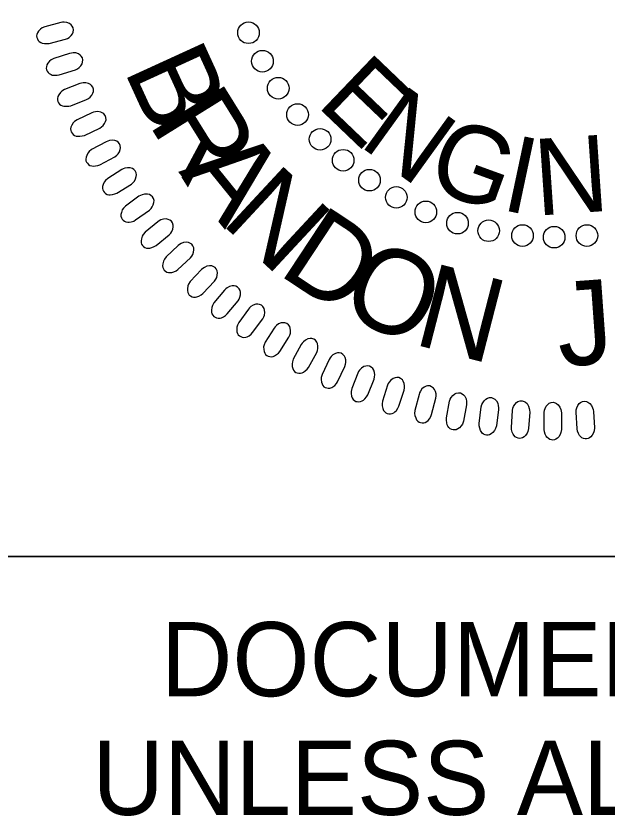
# Model space of a CAD drawing. Extents: x 505602 to 507705, y 483109 to 484209.
# Drawn here: x 507079.4 to 507123.2, y 484026.9 to 484086.2 of the extents above; entities that cross this region are included whole.
import ezdxf

# ---------------------------------------------------------------- set-up
doc = ezdxf.new("R2010")
doc.units = 0
for name, color, linetype in [('Sheet PE Seal Cell', 7, 'Continuous'), ('Sheet Profile CELL', 7, 'Continuous'), ('Sheet Sticker Exception Certification CELL', 7, 'Continuous')]:
    doc.layers.add(name, color=color, linetype=linetype)

msp = doc.modelspace()

# ---------------------------------------------------------------- linework, layer by layer
at = {"layer": 'Sheet PE Seal Cell'}
for points in [[(507082.689, 484085.753), (507081.501, 484085.449), (507081.298, 484085.358), (507081.175, 484085.273), (507081.039, 484085.122), (507080.957, 484085), (507080.907, 484084.872), (507080.895, 484084.761), (507080.903, 484084.647), (507080.95, 484084.544), (507081.009, 484084.435), (507081.093, 484084.349), (507081.216, 484084.272), (507081.308, 484084.234), (507081.469, 484084.206), (507081.658, 484084.193), (507081.818, 484084.21), (507083.037, 484084.515), (507083.196, 484084.579), (507083.32, 484084.657), (507083.452, 484084.784), (507083.56, 484084.927), (507083.613, 484085.04), (507083.632, 484085.208), (507083.614, 484085.358), (507083.538, 484085.492), (507083.464, 484085.582), (507083.336, 484085.68), (507083.142, 484085.753), (507082.951, 484085.775), (507082.818, 484085.771)], [(507083.343, 484083.469), (507082.176, 484083.09), (507081.979, 484082.987), (507081.862, 484082.895), (507081.735, 484082.735), (507081.661, 484082.609), (507081.62, 484082.478), (507081.615, 484082.366), (507081.63, 484082.253), (507081.684, 484082.153), (507081.749, 484082.049), (507081.838, 484081.967), (507081.966, 484081.899), (507082.059, 484081.866), (507082.223, 484081.849), (507082.412, 484081.847), (507082.571, 484081.875), (507083.768, 484082.256), (507083.922, 484082.33), (507084.042, 484082.415), (507084.165, 484082.55), (507084.263, 484082.699), (507084.31, 484082.817), (507084.318, 484082.984), (507084.291, 484083.133), (507084.207, 484083.263), (507084.127, 484083.347), (507083.993, 484083.437), (507083.795, 484083.498), (507083.603, 484083.507), (507083.471, 484083.495)], [(507084.102, 484081.232), (507082.961, 484080.781), (507082.77, 484080.665), (507082.659, 484080.566), (507082.543, 484080.399), (507082.477, 484080.268), (507082.444, 484080.134), (507082.446, 484080.023), (507082.468, 484079.911), (507082.528, 484079.815), (507082.6, 484079.714), (507082.693, 484079.639), (507082.825, 484079.578), (507082.921, 484079.552), (507083.086, 484079.544), (507083.274, 484079.555), (507083.431, 484079.592), (507084.602, 484080.047), (507084.752, 484080.131), (507084.865, 484080.224), (507084.98, 484080.366), (507085.069, 484080.522), (507085.108, 484080.641), (507085.105, 484080.81), (507085.069, 484080.956), (507084.977, 484081.08), (507084.892, 484081.159), (507084.753, 484081.241), (507084.551, 484081.289), (507084.359, 484081.286), (507084.228, 484081.266)], [(507085.001, 484079.073), (507083.891, 484078.551), (507083.709, 484078.423), (507083.604, 484078.317), (507083.499, 484078.143), (507083.441, 484078.008), (507083.416, 484077.873), (507083.425, 484077.761), (507083.454, 484077.651), (507083.52, 484077.559), (507083.598, 484077.463), (507083.697, 484077.394), (507083.832, 484077.342), (507083.929, 484077.321), (507084.093, 484077.324), (507084.281, 484077.347), (507084.435, 484077.394), (507085.576, 484077.922), (507085.719, 484078.015), (507085.827, 484078.114), (507085.932, 484078.263), (507086.012, 484078.424), (507086.043, 484078.546), (507086.03, 484078.714), (507085.984, 484078.858), (507085.884, 484078.976), (507085.794, 484079.049), (507085.651, 484079.122), (507085.446, 484079.157), (507085.255, 484079.143), (507085.125, 484079.114)], [(507086.049, 484076.924), (507084.973, 484076.333), (507084.799, 484076.195), (507084.702, 484076.082), (507084.607, 484075.902), (507084.558, 484075.764), (507084.542, 484075.628), (507084.557, 484075.516), (507084.594, 484075.408), (507084.666, 484075.32), (507084.75, 484075.23), (507084.852, 484075.167), (507084.99, 484075.123), (507085.089, 484075.109), (507085.252, 484075.122), (507085.438, 484075.156), (507085.589, 484075.213), (507086.694, 484075.811), (507086.832, 484075.913), (507086.932, 484076.02), (507087.029, 484076.175), (507087.097, 484076.34), (507087.121, 484076.464), (507087.097, 484076.63), (507087.043, 484076.771), (507086.936, 484076.883), (507086.842, 484076.951), (507086.693, 484077.014), (507086.487, 484077.037), (507086.297, 484077.01), (507086.169, 484076.973)], [(507087.205, 484074.85), (507086.169, 484074.192), (507086.003, 484074.043), (507085.914, 484073.925), (507085.83, 484073.739), (507085.79, 484073.598), (507085.783, 484073.46), (507085.805, 484073.351), (507085.848, 484073.245), (507085.926, 484073.162), (507086.015, 484073.077), (507086.121, 484073.02), (507086.261, 484072.985), (507086.36, 484072.978), (507086.523, 484073.001), (507086.707, 484073.047), (507086.853, 484073.113), (507087.919, 484073.779), (507088.05, 484073.889), (507088.144, 484074.003), (507088.23, 484074.163), (507088.288, 484074.333), (507088.304, 484074.458), (507088.27, 484074.622), (507088.207, 484074.759), (507088.093, 484074.864), (507087.995, 484074.925), (507087.842, 484074.98), (507087.635, 484074.99), (507087.447, 484074.95), (507087.322, 484074.906)], [(507088.482, 484072.875), (507087.488, 484072.153), (507087.333, 484071.994), (507087.25, 484071.87), (507087.179, 484071.68), (507087.148, 484071.537), (507087.149, 484071.399), (507087.178, 484071.291), (507087.228, 484071.188), (507087.31, 484071.11), (507087.405, 484071.03), (507087.515, 484070.98), (507087.657, 484070.955), (507087.756, 484070.953), (507087.917, 484070.987), (507088.097, 484071.043), (507088.24, 484071.119), (507089.261, 484071.851), (507089.385, 484071.969), (507089.471, 484072.088), (507089.548, 484072.254), (507089.595, 484072.426), (507089.603, 484072.552), (507089.559, 484072.714), (507089.487, 484072.847), (507089.367, 484072.944), (507089.265, 484073), (507089.11, 484073.045), (507088.903, 484073.041), (507088.717, 484072.99), (507088.595, 484072.939)], [(507089.885, 484070.993), (507088.939, 484070.211), (507088.794, 484070.043), (507088.72, 484069.914), (507088.661, 484069.719), (507088.638, 484069.574), (507088.648, 484069.437), (507088.684, 484069.331), (507088.74, 484069.232), (507088.827, 484069.159), (507088.926, 484069.085), (507089.039, 484069.042), (507089.182, 484069.026), (507089.282, 484069.03), (507089.44, 484069.074), (507089.616, 484069.142), (507089.754, 484069.226), (507090.727, 484070.021), (507090.844, 484070.146), (507090.922, 484070.27), (507090.988, 484070.441), (507091.025, 484070.616), (507091.024, 484070.742), (507090.97, 484070.901), (507090.89, 484071.029), (507090.764, 484071.118), (507090.659, 484071.167), (507090.501, 484071.202), (507090.295, 484071.187), (507090.113, 484071.124), (507089.994, 484071.064)], [(507091.395, 484069.222), (507090.5, 484068.383), (507090.366, 484068.206), (507090.3, 484068.072), (507090.253, 484067.874), (507090.24, 484067.728), (507090.258, 484067.592), (507090.301, 484067.488), (507090.363, 484067.393), (507090.454, 484067.325), (507090.558, 484067.258), (507090.673, 484067.223), (507090.818, 484067.215), (507090.916, 484067.226), (507091.072, 484067.279), (507091.244, 484067.358), (507091.375, 484067.451), (507092.296, 484068.305), (507092.405, 484068.438), (507092.476, 484068.566), (507092.531, 484068.74), (507092.556, 484068.918), (507092.548, 484069.043), (507092.484, 484069.199), (507092.396, 484069.321), (507092.265, 484069.403), (507092.157, 484069.445), (507091.997, 484069.47), (507091.792, 484069.441), (507091.614, 484069.367), (507091.5, 484069.3)], [(507093.131, 484067.444), (507092.29, 484066.55), (507092.167, 484066.365), (507092.11, 484066.227), (507092.075, 484066.027), (507092.071, 484065.88), (507092.098, 484065.745), (507092.147, 484065.645), (507092.215, 484065.553), (507092.31, 484065.491), (507092.419, 484065.431), (507092.535, 484065.403), (507092.68, 484065.404), (507092.778, 484065.421), (507092.93, 484065.484), (507093.096, 484065.574), (507093.222, 484065.675), (507094.088, 484066.586), (507094.187, 484066.724), (507094.25, 484066.857), (507094.294, 484067.035), (507094.308, 484067.213), (507094.292, 484067.338), (507094.219, 484067.489), (507094.123, 484067.606), (507093.987, 484067.679), (507093.876, 484067.714), (507093.716, 484067.729), (507093.513, 484067.687), (507093.34, 484067.602), (507093.23, 484067.528)], [(507094.821, 484065.914), (507094.038, 484064.969), (507093.927, 484064.776), (507093.878, 484064.635), (507093.856, 484064.433), (507093.862, 484064.286), (507093.897, 484064.154), (507093.952, 484064.056), (507094.026, 484063.969), (507094.124, 484063.914), (507094.236, 484063.86), (507094.354, 484063.839), (507094.499, 484063.85), (507094.596, 484063.872), (507094.743, 484063.945), (507094.903, 484064.045), (507095.023, 484064.154), (507095.83, 484065.117), (507095.921, 484065.262), (507095.974, 484065.399), (507096.008, 484065.578), (507096.011, 484065.757), (507095.986, 484065.881), (507095.903, 484066.027), (507095.801, 484066.138), (507095.661, 484066.202), (507095.547, 484066.23), (507095.386, 484066.235), (507095.187, 484066.18), (507095.019, 484066.085), (507094.914, 484066.004)], [(507096.601, 484064.514), (507095.88, 484063.521), (507095.781, 484063.322), (507095.741, 484063.178), (507095.732, 484062.975), (507095.747, 484062.828), (507095.79, 484062.698), (507095.851, 484062.605), (507095.93, 484062.522), (507096.033, 484062.473), (507096.148, 484062.427), (507096.267, 484062.413), (507096.41, 484062.433), (507096.506, 484062.462), (507096.648, 484062.544), (507096.802, 484062.654), (507096.914, 484062.769), (507097.659, 484063.781), (507097.74, 484063.931), (507097.786, 484064.071), (507097.808, 484064.252), (507097.8, 484064.432), (507097.767, 484064.553), (507097.676, 484064.694), (507097.566, 484064.798), (507097.422, 484064.854), (507097.308, 484064.875), (507097.147, 484064.869), (507096.95, 484064.802), (507096.79, 484064.696), (507096.69, 484064.609)], [(507098.503, 484063.1), (507097.846, 484062.064), (507097.759, 484061.859), (507097.728, 484061.714), (507097.732, 484061.51), (507097.756, 484061.366), (507097.808, 484061.238), (507097.874, 484061.148), (507097.959, 484061.072), (507098.063, 484061.028), (507098.181, 484060.989), (507098.301, 484060.984), (507098.443, 484061.012), (507098.536, 484061.047), (507098.673, 484061.137), (507098.82, 484061.256), (507098.924, 484061.379), (507099.604, 484062.436), (507099.676, 484062.591), (507099.713, 484062.733), (507099.723, 484062.916), (507099.703, 484063.094), (507099.663, 484063.213), (507099.564, 484063.349), (507099.448, 484063.445), (507099.3, 484063.491), (507099.185, 484063.505), (507099.025, 484063.49), (507098.833, 484063.411), (507098.679, 484063.295), (507098.585, 484063.202)], [(507100.521, 484061.885), (507099.93, 484060.81), (507099.857, 484060.6), (507099.835, 484060.452), (507099.852, 484060.25), (507099.884, 484060.106), (507099.944, 484059.982), (507100.016, 484059.897), (507100.105, 484059.826), (507100.212, 484059.789), (507100.332, 484059.758), (507100.452, 484059.759), (507100.592, 484059.797), (507100.683, 484059.837), (507100.814, 484059.936), (507100.953, 484060.065), (507101.05, 484060.194), (507101.662, 484061.291), (507101.723, 484061.45), (507101.751, 484061.595), (507101.75, 484061.777), (507101.72, 484061.954), (507101.673, 484062.071), (507101.564, 484062.199), (507101.442, 484062.288), (507101.292, 484062.325), (507101.176, 484062.332), (507101.017, 484062.306), (507100.831, 484062.215), (507100.685, 484062.09), (507100.596, 484061.991)], [(507102.58, 484060.778), (507102.058, 484059.669), (507101.998, 484059.454), (507101.986, 484059.306), (507102.015, 484059.104), (507102.056, 484058.963), (507102.124, 484058.844), (507102.201, 484058.763), (507102.295, 484058.697), (507102.404, 484058.668), (507102.525, 484058.644), (507102.645, 484058.653), (507102.783, 484058.699), (507102.871, 484058.745), (507102.995, 484058.852), (507103.126, 484058.989), (507103.215, 484059.124), (507103.757, 484060.257), (507103.808, 484060.421), (507103.827, 484060.566), (507103.814, 484060.749), (507103.773, 484060.923), (507103.718, 484061.036), (507103.602, 484061.157), (507103.474, 484061.239), (507103.323, 484061.267), (507103.206, 484061.266), (507103.049, 484061.23), (507102.869, 484061.128), (507102.732, 484060.993), (507102.65, 484060.889)], [(507104.708, 484059.77), (507104.256, 484058.63), (507104.21, 484058.412), (507104.207, 484058.263), (507104.249, 484058.064), (507104.298, 484057.926), (507104.374, 484057.811), (507104.456, 484057.735), (507104.553, 484057.675), (507104.664, 484057.652), (507104.787, 484057.636), (507104.906, 484057.652), (507105.04, 484057.708), (507105.125, 484057.759), (507105.243, 484057.874), (507105.364, 484058.018), (507105.444, 484058.158), (507105.914, 484059.324), (507105.956, 484059.49), (507105.965, 484059.636), (507105.941, 484059.817), (507105.888, 484059.988), (507105.827, 484060.099), (507105.703, 484060.212), (507105.571, 484060.286), (507105.418, 484060.303), (507105.302, 484060.295), (507105.147, 484060.25), (507104.974, 484060.136), (507104.845, 484059.994), (507104.77, 484059.885)], [(507106.917, 484058.868), (507106.537, 484057.701), (507106.505, 484057.481), (507106.511, 484057.332), (507106.565, 484057.136), (507106.624, 484057.002), (507106.706, 484056.891), (507106.793, 484056.821), (507106.894, 484056.767), (507107.006, 484056.752), (507107.13, 484056.743), (507107.247, 484056.767), (507107.378, 484056.831), (507107.459, 484056.888), (507107.57, 484057.009), (507107.682, 484057.161), (507107.753, 484057.306), (507108.149, 484058.498), (507108.18, 484058.667), (507108.18, 484058.814), (507108.144, 484058.993), (507108.081, 484059.16), (507108.013, 484059.266), (507107.882, 484059.372), (507107.746, 484059.437), (507107.592, 484059.445), (507107.477, 484059.43), (507107.325, 484059.375), (507107.159, 484059.251), (507107.039, 484059.1), (507106.971, 484058.986)], [(507109.25, 484058.195), (507108.944, 484057.007), (507108.926, 484056.786), (507108.941, 484056.637), (507109.008, 484056.444), (507109.074, 484056.314), (507109.164, 484056.209), (507109.255, 484056.144), (507109.358, 484056.097), (507109.472, 484056.089), (507109.595, 484056.088), (507109.711, 484056.119), (507109.837, 484056.19), (507109.915, 484056.252), (507110.018, 484056.381), (507110.12, 484056.54), (507110.182, 484056.689), (507110.502, 484057.904), (507110.522, 484058.073), (507110.513, 484058.22), (507110.466, 484058.397), (507110.393, 484058.56), (507110.318, 484058.661), (507110.181, 484058.759), (507110.042, 484058.815), (507109.886, 484058.814), (507109.773, 484058.791), (507109.625, 484058.727), (507109.467, 484058.592), (507109.357, 484058.435), (507109.296, 484058.317)], [(507112.772, 484057.407), (507112.541, 484056.202), (507112.463, 484055.994), (507112.386, 484055.866), (507112.244, 484055.721), (507112.128, 484055.632), (507112.003, 484055.574), (507111.892, 484055.554), (507111.778, 484055.557), (507111.673, 484055.597), (507111.56, 484055.649), (507111.469, 484055.727), (507111.385, 484055.845), (507111.341, 484055.934), (507111.303, 484056.094), (507111.278, 484056.282), (507111.286, 484056.442), (507111.514, 484057.678), (507111.568, 484057.841), (507111.639, 484057.969), (507111.757, 484058.109), (507111.893, 484058.225), (507112.003, 484058.285), (507112.168, 484058.314), (507112.32, 484058.306), (507112.458, 484058.238), (507112.552, 484058.17), (507112.658, 484058.049), (507112.743, 484057.859), (507112.776, 484057.67), (507112.781, 484057.538)], [(507115.138, 484057.081), (507114.983, 484055.864), (507114.919, 484055.652), (507114.849, 484055.519), (507114.717, 484055.365), (507114.607, 484055.268), (507114.485, 484055.203), (507114.377, 484055.177), (507114.263, 484055.172), (507114.155, 484055.205), (507114.039, 484055.25), (507113.943, 484055.322), (507113.852, 484055.435), (507113.802, 484055.521), (507113.754, 484055.678), (507113.718, 484055.864), (507113.715, 484056.025), (507113.866, 484057.272), (507113.909, 484057.437), (507113.972, 484057.571), (507114.08, 484057.717), (507114.209, 484057.842), (507114.316, 484057.909), (507114.479, 484057.949), (507114.63, 484057.949), (507114.773, 484057.891), (507114.871, 484057.828), (507114.985, 484057.714), (507115.081, 484057.531), (507115.126, 484057.344), (507115.139, 484057.211)], [(507117.455, 484056.884), (507117.377, 484055.659), (507117.326, 484055.443), (507117.265, 484055.307), (507117.143, 484055.144), (507117.039, 484055.041), (507116.922, 484054.969), (507116.815, 484054.935), (507116.701, 484054.923), (507116.591, 484054.95), (507116.474, 484054.987), (507116.373, 484055.053), (507116.275, 484055.16), (507116.22, 484055.243), (507116.162, 484055.397), (507116.114, 484055.579), (507116.102, 484055.74), (507116.173, 484056.995), (507116.207, 484057.162), (507116.261, 484057.299), (507116.36, 484057.452), (507116.48, 484057.585), (507116.583, 484057.658), (507116.743, 484057.708), (507116.894, 484057.718), (507117.041, 484057.669), (507117.141, 484057.613), (507117.262, 484057.505), (507117.37, 484057.328), (507117.427, 484057.144), (507117.448, 484057.014)], [(507122.175, 484056.934), (507122.251, 484055.71), (507122.228, 484055.489), (507122.185, 484055.346), (507122.083, 484055.169), (507121.994, 484055.054), (507121.886, 484054.968), (507121.785, 484054.921), (507121.674, 484054.894), (507121.561, 484054.908), (507121.44, 484054.93), (507121.331, 484054.983), (507121.22, 484055.076), (507121.156, 484055.152), (507121.08, 484055.297), (507121.009, 484055.472), (507120.976, 484055.63), (507120.89, 484056.884), (507120.902, 484057.055), (507120.938, 484057.197), (507121.018, 484057.361), (507121.121, 484057.508), (507121.213, 484057.593), (507121.366, 484057.663), (507121.514, 484057.692), (507121.665, 484057.662), (507121.773, 484057.619), (507121.906, 484057.527), (507122.036, 484057.365), (507122.115, 484057.19), (507122.153, 484057.063)], [(507119.808, 484056.812), (507119.808, 484055.585), (507119.77, 484055.366), (507119.718, 484055.226), (507119.606, 484055.056), (507119.508, 484054.947), (507119.396, 484054.867), (507119.292, 484054.827), (507119.18, 484054.808), (507119.068, 484054.828), (507118.948, 484054.857), (507118.843, 484054.917), (507118.738, 484055.017), (507118.679, 484055.097), (507118.611, 484055.247), (507118.552, 484055.426), (507118.529, 484055.586), (507118.522, 484056.842), (507118.545, 484057.011), (507118.59, 484057.151), (507118.679, 484057.311), (507118.791, 484057.45), (507118.889, 484057.53), (507119.046, 484057.59), (507119.196, 484057.61), (507119.345, 484057.57), (507119.45, 484057.52), (507119.577, 484057.421), (507119.696, 484057.251), (507119.764, 484057.071), (507119.793, 484056.941)]]:
    msp.add_lwpolyline(points, close=True, dxfattribs=at)
for centre in [(507096.606, 484085.001), (507097.641, 484082.889), (507098.81, 484080.886), (507100.242, 484078.933), (507101.914, 484077.1), (507103.625, 484075.546), (507105.576, 484074.071), (507107.566, 484072.796), (507109.755, 484071.719), (507112.104, 484070.882), (507114.413, 484070.324), (507116.921, 484069.964), (507121.699, 484069.963), (507119.27, 484069.844)]:
    msp.add_circle(centre, 0.801, dxfattribs=at)
at = {"layer": 'Sheet Profile CELL'}
msp.add_lwpolyline([(507069.03, 484158.662), (507169.08, 484158.662), (507169.08, 484046.162), (507069.03, 484046.162)], close=True, dxfattribs=at)
at = {"layer": 'Sheet Sticker Exception Certification CELL'}
msp.add_line((507069.03, 484046.162), (507269.067, 484046.162), dxfattribs=at)
msp.add_line((507069.03, 484046.162), (507269.067, 484046.162), dxfattribs=at)

# ---------------------------------------------------------------- texts
at = {"layer": 'Sheet PE Seal Cell'}
for s, height, rotation, p in [('B', 6.236, 294.5897, (507087.323, 484082.272)), ('E', 5.669, 316.26559, (507101.563, 484079.651)), ('R', 6.236, 301.86473, (507089.134, 484078.316)), ('N', 5.669, 324.20538, (507104.698, 484076.696)), ('G', 5.669, 340.08498, (507109.592, 484073.597)), ('I', 5.669, 348.02477, (507115.221, 484071.908)), ('N', 5.669, 3.90437, (507117.974, 484071.435)), ('A', 6.236, 308.98157, (507091.377, 484074.698)), ('N', 6.236, 317.09274, (507094.456, 484070.95)), ('D', 6.236, 326.58243, (507098.686, 484067.169)), ('O', 6.236, 335.45066, (507103.152, 484064.311)), ('N', 6.236, 345.5505, (507108.704, 484061.939)), ('J', 6.236, 4.1457, (507119.655, 484060.247))]:
    msp.add_text(s, height=height, rotation=rotation, dxfattribs=at).set_placement(p)
at = {"layer": 'Sheet Sticker Exception Certification CELL'}
for s, p in [('DOCUMENT NOT CONSIDERED FINAL', (507090.101, 484035.816)), ('DOCUMENT NOT CONSIDERED FINAL', (507090.101, 484035.816)), ('UNLESS ALL SIGNATURES COMPLETED', (507085.03, 484027.016)), ('UNLESS ALL SIGNATURES COMPLETED', (507085.03, 484027.016))]:
    msp.add_text(s, height=5.5, dxfattribs=at).set_placement(p)

doc.saveas('drawing.dxf')
